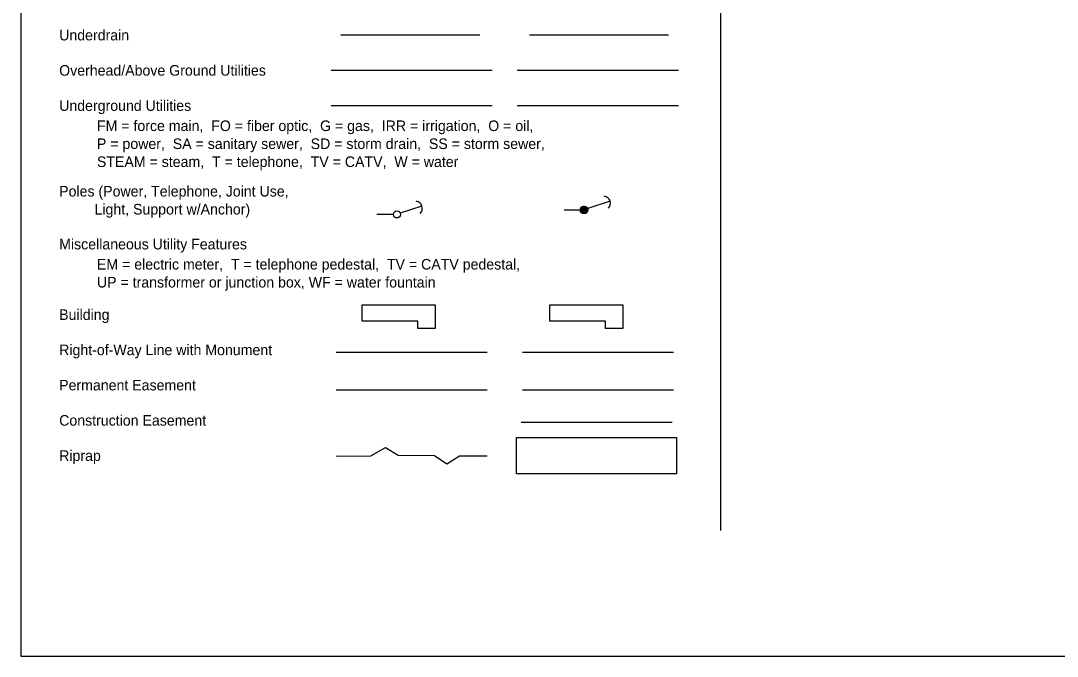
# Model space of a CAD drawing. Extents: x 0 to 2.72, y -0.06 to 0.86.
# Drawn here: x 1.425 to 2.111, y -0.002 to 0.419 of the extents above; entities that cross this region are included whole.
import ezdxf

# ---------------------------------------------------------------- set-up
doc = ezdxf.new("R2010")
doc.units = 0
for name, color, linetype in [('AUX_09', 7, 'Continuous'), ('D_Details', 7, 'Continuous'), ('D_Dimensions', 7, 'Continuous'), ('Default', 7, 'Continuous'), ('E_GEO_Rip_Rap', 7, 'Continuous'), ('E_HYD_Underdrains', 7, 'Continuous'), ('E_PLM_Structure', 7, 'Continuous'), ('E_RW_Perm_Easement', 7, 'Continuous'), ('E_RW_Right_of_Way_Line', 7, 'Continuous'), ('E_UT_Overhead_Power', 7, 'Continuous'), ('E_UT_Pole_Supports', 7, 'Continuous'), ('E_UT_Underground_Water', 7, 'Continuous'), ('P_HYD_Underdrains', 7, 'Continuous'), ('P_RW_Construction_Easement', 7, 'Continuous'), ('P_RW_Permanent_Easement', 7, 'Continuous'), ('P_RW_Right_of_Way', 7, 'Continuous'), ('P_STR_Build_and_Structures', 7, 'Continuous'), ('P_UT_Overhead_Power_Line', 7, 'Continuous'), ('P_UT_Underground_Water', 7, 'Continuous')]:
    doc.layers.add(name, color=color, linetype=linetype)

msp = doc.modelspace()

# ---------------------------------------------------------------- linework, layer by layer
at = {"layer": 'AUX_09'}
for p, q in [((1.81506, 0.29922), (1.80039, 0.29437)), ((1.81506, 0.29922), (1.80039, 0.29437)), ((1.79541, 0.2933), (1.78452, 0.2933)), ((1.79541, 0.2933), (1.78452, 0.2933))]:
    msp.add_line(p, q, dxfattribs=at)
for points in [[(1.79624, 0.29514), (1.79624, 0.29514), (1.79612, 0.29171), (1.79612, 0.29159)], [(1.79624, 0.29514), (1.79624, 0.29514), (1.79612, 0.29171), (1.79612, 0.29159)], [(1.79642, 0.29543), (1.79642, 0.29141)], [(1.79642, 0.29543), (1.79642, 0.29141)], [(1.79666, 0.29549), (1.79666, 0.29549), (1.79666, 0.29123), (1.79666, 0.29123)], [(1.79666, 0.29549), (1.79666, 0.29549), (1.79666, 0.29123), (1.79666, 0.29123)], [(1.79695, 0.29567), (1.79695, 0.29106)], [(1.79695, 0.29567), (1.79695, 0.29106)], [(1.79719, 0.29579), (1.79719, 0.291)], [(1.79719, 0.29579), (1.79719, 0.291)], [(1.79737, 0.29585), (1.79737, 0.29088)], [(1.79737, 0.29585), (1.79737, 0.29088)], [(1.79766, 0.29597), (1.79766, 0.29585), (1.79766, 0.29088), (1.79766, 0.29088)], [(1.79766, 0.29597), (1.79766, 0.29585), (1.79766, 0.29088), (1.79766, 0.29088)], [(1.7979, 0.29082), (1.7979, 0.29597)], [(1.7979, 0.29082), (1.7979, 0.29597)], [(1.79819, 0.29585), (1.79819, 0.29585), (1.79819, 0.29088), (1.79819, 0.29082)], [(1.79819, 0.29585), (1.79819, 0.29585), (1.79819, 0.29088), (1.79819, 0.29082)], [(1.79843, 0.29585), (1.79843, 0.291)], [(1.79843, 0.29585), (1.79843, 0.291)], [(1.79861, 0.29579), (1.79861, 0.291)], [(1.79861, 0.29579), (1.79861, 0.291)], [(1.7989, 0.29567), (1.7989, 0.29106)], [(1.7989, 0.29567), (1.7989, 0.29106)], [(1.79914, 0.29549), (1.79914, 0.29549), (1.79914, 0.29123), (1.79914, 0.29123)], [(1.79914, 0.29549), (1.79914, 0.29549), (1.79914, 0.29123), (1.79914, 0.29123)], [(1.79944, 0.29532), (1.79944, 0.29141)], [(1.79944, 0.29532), (1.79944, 0.29141)], [(1.79967, 0.29514), (1.79967, 0.29508), (1.79961, 0.29159), (1.79961, 0.29159)], [(1.79967, 0.29514), (1.79967, 0.29508), (1.79961, 0.29159), (1.79961, 0.29159)], [(1.79571, 0.29455), (1.79571, 0.29437), (1.79559, 0.29242), (1.79559, 0.2923)], [(1.79571, 0.29455), (1.79571, 0.29437), (1.79559, 0.29242), (1.79559, 0.2923)], [(1.79595, 0.2949), (1.79595, 0.29478), (1.79589, 0.29194), (1.79589, 0.29194)], [(1.79595, 0.2949), (1.79595, 0.29478), (1.79589, 0.29194), (1.79589, 0.29194)], [(1.79997, 0.2949), (1.79997, 0.29478), (1.79985, 0.29194), (1.79985, 0.29188)], [(1.79997, 0.2949), (1.79997, 0.29478), (1.79985, 0.29194), (1.79985, 0.29188)], [(1.80021, 0.29455), (1.80021, 0.29425), (1.80015, 0.29242), (1.80015, 0.29224)], [(1.80021, 0.29455), (1.80021, 0.29425), (1.80015, 0.29242), (1.80015, 0.29224)]]:
    msp.add_lwpolyline(points, dxfattribs=at)
msp.add_circle((1.79775, 0.29339), 0.0025, dxfattribs=at)
msp.add_circle((1.79775, 0.29339), 0.0025, dxfattribs=at)
msp.add_arc((1.81066, 0.29781), 0.00466, 313.52233, 83.34883, dxfattribs=at)
msp.add_arc((1.81066, 0.29781), 0.00466, 313.52233, 83.34883, dxfattribs=at)
at = {"layer": 'D_Details'}
msp.add_line((1.88821, 0.85833), (1.88821, 0.08127), dxfattribs=at)
at = {"layer": 'D_Dimensions'}
msp.add_lwpolyline([(1.75308, 0.14267), (1.85901, 0.14267), (1.85901, 0.11879), (1.75308, 0.11879)], close=True, dxfattribs=at)
msp.add_lwpolyline([(1.75308, 0.14267), (1.85901, 0.14267), (1.85901, 0.11879), (1.75308, 0.11879)], close=True, dxfattribs=at)
at = {"layer": 'Default'}
msp.add_lwpolyline([(1.42482, -0.00206), (2.72482, -0.00206), (2.72482, 0.86461), (1.42482, 0.86461)], close=True, dxfattribs=at)
at = {"layer": 'E_GEO_Rip_Rap'}
msp.add_lwpolyline([(1.6336, 0.13042), (1.65652, 0.13065), (1.6663, 0.13617), (1.67481, 0.13108), (1.69882, 0.1309), (1.70701, 0.1253), (1.71538, 0.13057), (1.7336, 0.13064)], dxfattribs=at)
at = {"layer": 'E_HYD_Underdrains'}
msp.add_line((1.63673, 0.40923), (1.7288, 0.40923), dxfattribs=at)
at = {"layer": 'E_PLM_Structure'}
msp.add_lwpolyline([(1.65084, 0.2305), (1.69914, 0.23055), (1.69914, 0.21487), (1.68766, 0.21487), (1.68766, 0.21984), (1.65084, 0.21984)], close=True, dxfattribs=at)
msp.add_lwpolyline([(1.65084, 0.2305), (1.69914, 0.23055), (1.69914, 0.21487), (1.68766, 0.21487), (1.68766, 0.21984), (1.65084, 0.21984)], close=True, dxfattribs=at)
at = {"layer": 'E_RW_Perm_Easement'}
msp.add_line((1.6336, 0.17423), (1.7336, 0.17423), dxfattribs=at)
at = {"layer": 'E_RW_Right_of_Way_Line'}
msp.add_line((1.6336, 0.19923), (1.7336, 0.19923), dxfattribs=at)
at = {"layer": 'E_UT_Overhead_Power'}
msp.add_line((1.63027, 0.3859), (1.73693, 0.3859), dxfattribs=at)
at = {"layer": 'E_UT_Pole_Supports'}
for p, q in [((1.69041, 0.29585), (1.67608, 0.29112)), ((1.69041, 0.29585), (1.67608, 0.29112)), ((1.67158, 0.29035), (1.66057, 0.29035)), ((1.67158, 0.29035), (1.66057, 0.29035))]:
    msp.add_line(p, q, dxfattribs=at)
msp.add_circle((1.67392, 0.29037), 0.00233, dxfattribs=at)
msp.add_circle((1.67392, 0.29037), 0.00233, dxfattribs=at)
msp.add_arc((1.68604, 0.29444), 0.00466, 313.52233, 83.34883, dxfattribs=at)
msp.add_arc((1.68604, 0.29444), 0.00466, 313.52233, 83.34883, dxfattribs=at)
at = {"layer": 'E_UT_Underground_Water'}
msp.add_line((1.63027, 0.36257), (1.73693, 0.36257), dxfattribs=at)
at = {"layer": 'P_HYD_Underdrains'}
msp.add_line((1.76173, 0.40923), (1.8538, 0.40923), dxfattribs=at)
at = {"layer": 'P_RW_Construction_Easement'}
msp.add_line((1.75605, 0.15278), (1.85605, 0.15278), dxfattribs=at)
at = {"layer": 'P_RW_Permanent_Easement'}
msp.add_line((1.75693, 0.17423), (1.85693, 0.17423), dxfattribs=at)
at = {"layer": 'P_RW_Right_of_Way'}
msp.add_line((1.75693, 0.19923), (1.85693, 0.19923), dxfattribs=at)
at = {"layer": 'P_STR_Build_and_Structures'}
msp.add_lwpolyline([(1.77515, 0.2305), (1.82345, 0.2305), (1.82345, 0.21487), (1.81202, 0.21487), (1.81202, 0.21984), (1.77515, 0.21984)], close=True, dxfattribs=at)
msp.add_lwpolyline([(1.77515, 0.2305), (1.82345, 0.2305), (1.82345, 0.21487), (1.81202, 0.21487), (1.81202, 0.21984), (1.77515, 0.21984)], close=True, dxfattribs=at)
at = {"layer": 'P_UT_Overhead_Power_Line'}
msp.add_line((1.7536, 0.3859), (1.86027, 0.3859), dxfattribs=at)
at = {"layer": 'P_UT_Underground_Water'}
msp.add_line((1.7536, 0.36257), (1.86027, 0.36257), dxfattribs=at)

# ---------------------------------------------------------------- texts
at = {"layer": 'D_Dimensions'}
for s, p in [('Underdrain', (1.45027, 0.40557)), ('Overhead/Above Ground Utilities', (1.45027, 0.38223)), ('Underground Utilities', (1.45027, 0.3589)), ('FM = force main,  FO = fiber optic,  G = gas,  IRR = irrigation,  O = oil,  ', (1.47527, 0.34557)), ('P = power,  SA = sanitary sewer,  SD = storm drain,  SS = storm sewer,  ', (1.47527, 0.33367)), ('STEAM = steam,  T = telephone,  TV = CATV,  W = water', (1.47527, 0.32177)), ('Poles (Power, Telephone, Joint Use,', (1.45027, 0.30223)), ('         Light, Support w/Anchor)', (1.45027, 0.29033)), ('Miscellaneous Utility Features', (1.45027, 0.26723)), ('EM = electric meter,  T = telephone pedestal,  TV = CATV pedestal, ', (1.47527, 0.2539)), ('UP = transformer or junction box, WF = water fountain', (1.47527, 0.242)), ('Building', (1.45027, 0.22057)), ('Right-of-Way Line with Monument', (1.45027, 0.19723)), ('Permanent Easement', (1.45027, 0.1739)), ('Construction Easement', (1.45027, 0.15057)), ('Riprap', (1.45027, 0.12723))]:
    msp.add_text(s, height=0.007, dxfattribs=at).set_placement(p)

doc.saveas('drawing.dxf')
